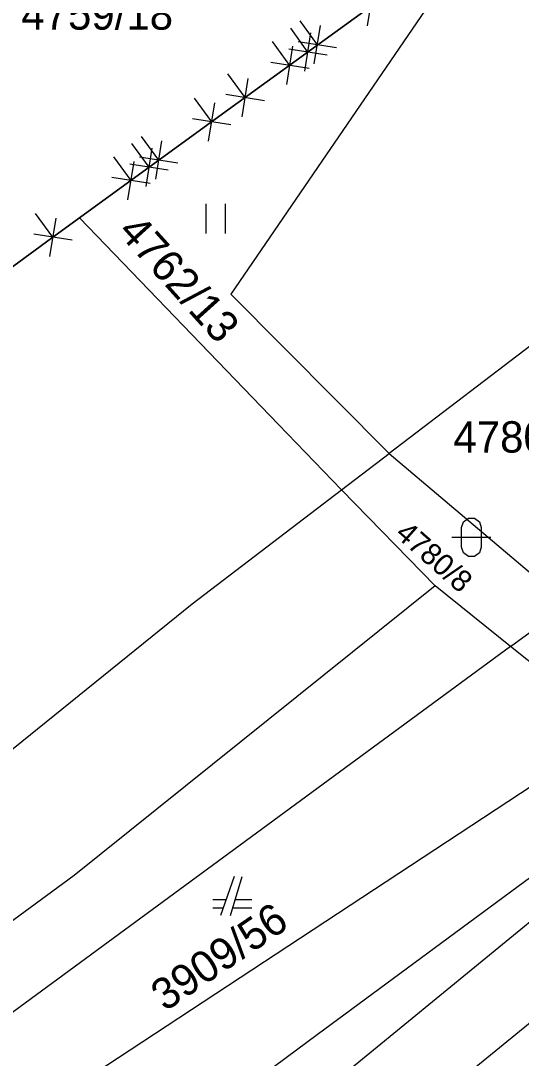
# Model space of a CAD drawing. Extents: x -266179 to -264727, y -1243225 to -1241702.
# Drawn here: x -265443.1 to -265417.6, y -1242998.6 to -1242945.7 of the extents above; entities that cross this region are included whole.
import ezdxf

# ---------------------------------------------------------------- set-up
doc = ezdxf.new("R2010")
doc.units = 0
for name, color, linetype in [('Vrstva 1', 7, 'Continuous'), ('Vrstva 2', 7, 'Continuous'), ('Vrstva 21', 7, 'Continuous')]:
    doc.layers.add(name, color=color, linetype=linetype)

msp = doc.modelspace()

# ---------------------------------------------------------------- linework, layer by layer
at = {"layer": 'Vrstva 1'}
for p, q in [((-265432.53, -1242950.23), (-265419.55, -1242940.8)), ((-265419.55, -1242940.8), (-265432.41, -1242959.64)), ((-265397.77, -1242947.47), (-265424.35, -1242967.76)), ((-265437.44, -1242953.79), (-265432.53, -1242950.23)), ((-265440.13, -1242955.75), (-265437.44, -1242953.79)), ((-265433.69, -1242955.04), (-265433.69, -1242956.54)), ((-265432.69, -1242956.54), (-265432.69, -1242955.04)), ((-265441.55, -1242956.78), (-265440.13, -1242955.75)), ((-265440.13, -1242955.75), (-265429.98, -1242966.29)), ((-265485.47, -1242988.9), (-265441.55, -1242956.78)), ((-265432.41, -1242959.64), (-265424.35, -1242967.76)), ((-265429.98, -1242966.29), (-265426.77, -1242969.61)), ((-265426.77, -1242969.61), (-265424.35, -1242967.76)), ((-265424.35, -1242967.76), (-265416.44, -1242974.44)), ((-265434.39, -1242975.43), (-265426.77, -1242969.61)), ((-265422.01, -1242974.52), (-265426.77, -1242969.61)), ((-265422.01, -1242974.52), (-265440.4, -1242989.28)), ((-265418.16, -1242977.61), (-265422.01, -1242974.52)), ((-265475.52, -1243008.72), (-265434.39, -1242975.43)), ((-265418.16, -1242977.61), (-265415.16, -1242975.4)), ((-265418.16, -1242977.61), (-265445.92, -1242998.02)), ((-265412.81, -1242981.9), (-265418.16, -1242977.61)), ((-265455.74, -1243010.14), (-265412.81, -1242981.9)), ((-265409.93, -1242984.03), (-265428.01, -1242997.42)), ((-265440.4, -1242989.28), (-265479.04, -1243017.66)), ((-265432.24, -1242989.33), (-265432.94, -1242991.33)), ((-265432.44, -1242991.33), (-265431.84, -1242989.33)), ((-265432.66, -1242990.53), (-265433.34, -1242990.53)), ((-265433.34, -1242990.93), (-265432.8, -1242990.93)), ((-265432.32, -1242990.93), (-265431.34, -1242990.93)), ((-265431.34, -1242990.53), (-265432.2, -1242990.53)), ((-265428.01, -1242997.42), (-265439.81, -1243006.11))]:
    msp.add_line(p, q, dxfattribs=at)
msp.add_lwpolyline([(-265420.66, -1242971.54), (-265420.56, -1242971.25), (-265420.31, -1242971.07), (-265420, -1242971.07), (-265419.75, -1242971.25), (-265419.65, -1242971.54), (-265419.65, -1242972.54), (-265419.75, -1242972.83), (-265420, -1242973.01), (-265420.31, -1242973.01), (-265420.56, -1242972.83), (-265420.66, -1242972.54)], close=True, dxfattribs=at)
msp.add_lwpolyline([(-265421.16, -1242972.04), (-265419.89, -1242972.04), (-265419.16, -1242972.04)], dxfattribs=at)
at = {"layer": 'Vrstva 2'}
for p, q in [((-265412.54, -1242987.85), (-265434.31, -1243005.69)), ((-265410.05, -1242990.99), (-265431.82, -1243008.76))]:
    msp.add_line(p, q, dxfattribs=at)
at = {"layer": 'Vrstva 21'}
for p, q in [((-265419.55, -1242940.8), (-265432.53, -1242950.23)), ((-265432.53, -1242950.23), (-265419.55, -1242940.8)), ((-265425.452, -1242945.962), (-265425.141, -1242944.007)), ((-265428.006, -1242946.918), (-265428.889, -1242945.705)), ((-265428.16, -1242947.896), (-265427.852, -1242945.94)), ((-265428.484, -1242947.292), (-265429.366, -1242946.078)), ((-265428.639, -1242948.269), (-265428.33, -1242946.314)), ((-265429.407, -1242947.973), (-265430.288, -1242946.759)), ((-265429.563, -1242948.951), (-265429.252, -1242946.996)), ((-265427.028, -1242947.072), (-265428.984, -1242946.764)), ((-265427.507, -1242947.446), (-265429.462, -1242947.137)), ((-265428.43, -1242948.129), (-265430.385, -1242947.817)), ((-265431.685, -1242949.617), (-265432.567, -1242948.403)), ((-265431.84, -1242950.595), (-265431.53, -1242948.639)), ((-265433.392, -1242950.855), (-265434.272, -1242949.641)), ((-265430.707, -1242949.772), (-265432.663, -1242949.462)), ((-265432.53, -1242950.23), (-265437.44, -1242953.79)), ((-265437.44, -1242953.79), (-265432.53, -1242950.23)), ((-265433.548, -1242951.833), (-265433.236, -1242949.878)), ((-265432.414, -1242951.011), (-265434.369, -1242950.7)), ((-265436.09, -1242952.804), (-265436.973, -1242951.592)), ((-265436.244, -1242953.782), (-265435.936, -1242951.827)), ((-265436.578, -1242953.165), (-265437.459, -1242951.95)), ((-265436.734, -1242954.142), (-265436.422, -1242952.187)), ((-265437.503, -1242953.844), (-265438.384, -1242952.629)), ((-265437.659, -1242954.821), (-265437.347, -1242952.866)), ((-265435.112, -1242952.958), (-265437.068, -1242952.651)), ((-265435.601, -1242953.32), (-265437.556, -1242953.009)), ((-265437.44, -1242953.79), (-265440.13, -1242955.75)), ((-265440.13, -1242955.75), (-265437.44, -1242953.79)), ((-265436.525, -1242953.999), (-265438.481, -1242953.688)), ((-265441.48, -1242956.736), (-265442.363, -1242955.523)), ((-265441.634, -1242957.713), (-265441.326, -1242955.758)), ((-265440.13, -1242955.75), (-265441.55, -1242956.78)), ((-265441.55, -1242956.78), (-265440.13, -1242955.75)), ((-265440.502, -1242956.889), (-265442.458, -1242956.582)), ((-265441.55, -1242956.78), (-265485.47, -1242988.9)), ((-265485.47, -1242988.9), (-265441.55, -1242956.78))]:
    msp.add_line(p, q, dxfattribs=at)

# ---------------------------------------------------------------- texts
at = {"layer": 'Vrstva 1'}
for s, p in [('4759/18', (-265443.094, -1242946.15)), ('4780/7', (-265421.072, -1242967.72))]:
    msp.add_text(s, height=1.6, dxfattribs=at).set_placement(p)
for s, height, rotation, p in [('4762/13', 1.6, 312.0328, (-265438.229, -1242956.497)), ('4780/8', 1.1, 318.5645, (-265424.094, -1242971.952)), ('3909/56', 1.6, 34.2629, (-265435.766, -1242996.253))]:
    msp.add_text(s, height=height, rotation=rotation, dxfattribs=at).set_placement(p)

doc.saveas('drawing.dxf')
